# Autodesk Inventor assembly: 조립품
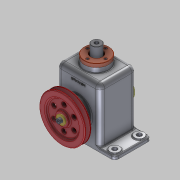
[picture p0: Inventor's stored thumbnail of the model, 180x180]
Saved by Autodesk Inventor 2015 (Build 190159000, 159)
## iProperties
Created: 2023-04
Part Number: 조립품
Document SubType Name: Assembly
Designer: SCD-A08
Mass: 5578.42 g
Surface Area: 3316.76 cm^2
Volume: 1337.01 cm^3
Density: 4.17231 g/cm^3
Author: SCD-A08
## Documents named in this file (20)
- C:\Users\SCD-A08\Desktop\630407V1017\조립품.iam
- C:\Users\SCD-A08\Desktop\630407V1017\본체.ipt
- C:\Users\SCD-A08\Desktop\630407V1017\뒷커버.ipt
- C:\Users\SCD-A08\Desktop\630407V1017\베어링 6205.ipt
- 베어링 6205.ipt
- C:\Users\SCD-A08\Desktop\630407V1017\볼트 M4 x 12.ipt
- C:\Users\SCD-A08\Desktop\630407V1017\V-벨트풀리.ipt
- C:\Users\SCD-A08\Desktop\630407V1017\멈춤링 25 x 1.2.ipt
- 멈춤링 25 x 1.2.ipt
- C:\Users\SCD-A08\Desktop\630407V1017\볼트 M8 x 16.ipt
- C:\Users\SCD-A08\Desktop\630407V1017\앞커버.ipt
- C:\Users\SCD-A08\Desktop\630407V1017\엔드캡.ipt
- C:\Users\SCD-A08\Desktop\630407V1017\오일실 25 40 8.ipt
- 오일실 25 40 8.ipt
- C:\Users\SCD-A08\Desktop\630407V1017\키 6x6x14.ipt
- C:\Users\SCD-A08\Desktop\630407V1017\편심축.ipt
- C:\Users\SCD-A08\Desktop\630407V1017\부시.ipt
- C:\Users\SCD-A08\Desktop\630407V1017\슬라이더.ipt
- C:\Users\SCD-A08\Desktop\630407V1017\윗커버.ipt
- C:\Users\SCD-A08\Desktop\630407V1017\가변스프링.ipt
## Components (2 placed, 2 different names)
1. V-벨트풀리:1 — 각도:1
2. 가변스프링:1
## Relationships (1: Angle 1)
- 각도:1 [Angle]: V-벨트풀리:1
